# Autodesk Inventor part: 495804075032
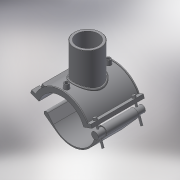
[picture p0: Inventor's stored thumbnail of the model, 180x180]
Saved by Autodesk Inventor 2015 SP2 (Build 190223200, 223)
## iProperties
Created: 2017-07
Part Number: 495804075032
Material: Generic
Description: PLASSON BRANCH SADDLE 75-32
Document SubType Name: Modeling
Designer: KIM
Density: 1 g/cm^3
Appearance: Default
Author: KIM
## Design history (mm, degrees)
derived "495804.ipt"
feature "Solid1::495804.ipt"
feature "Solid2::495804.ipt"
tag "TaggingFeature1"
body "Solid1"
body "Solid2"
other parameters: "d0" = 75, "d2" = 117, "d3" = 18.75, "d4" = 118, "d5" = 0, "d6" = 0.1, "d8" = 0, "d19" = 6, "d20" = 6, "d21" = 70.8, "d23" = 0, "d24" = 35.4, "d26" = 0, "d27" = 3, "d28" = 3, "d29" = 3, "d30" = 25, "d31" = 6, "d32" = 0, "d33" = 0, "d34" = 0.6, "d40" = 49.4, "d41" = 35.2, "d43" = 0, "d45" = 0, "d47" = 106.5, "d48" = 32, "d50" = 0, "d70" = 15, "d72" = 0, "d73" = 6, "d75" = 5, "d76" = 0, "d77" = 3.75, "d78" = 67.5, "d79" = 15, "d80" = 47.2, "d82" = 5 deg, "d84" = 4, "d85" = 14, "d86" = 0, "d87" = 3, "d88" = 0, "d89" = 1, "d90" = 1, "d91" = 94.4, "d92" = 0, "d93" = 0.5, "d94" = 39.47368, "d96" = 96.9, "d97" = 2.36, "d98" = 0, "d102" = 0.96, "d103" = 25.6, "d105" = 0, "d109" = -19.66667, "d117" = 0.32, "d120" = 140 deg, "d121" = 24.228, "d122" = 20 deg, "d124" = 57, "d126" = 0, "d143" = 78.75, "d150" = 13.5, "d159" = 4, "d161" = 1.875, "d162" = 70.8, "d163" = 0, "d167" = 15, "d168" = 43.18182, "d173" = 1, "d175" = 37.5, "d176" = 20 deg, "d177" = 5.25, "d180" = 0, "d185" = 38.35, "d186" = 38.35, "d187" = 47.5, "d188" = 6, "d189" = 5.25, "d190" = 0, "d191" = 71.25, "d202" = 0, "d216" = 106.2, "d217" = 0, "d221" = 43.66, "d222" = 5.25, "d223" = 3.15, "d224" = 37.5, "d225" = 3.15, "d227" = 10.8, "d230" = 46.5, "d236" = 20 deg, "d237" = 54.5, "d238" = 20 deg, "d239" = 5.25, "d_" = 75, "B_" = 117, "H_" = 59, "L_" = 118, "d_t" = 6, "d_1" = 32, "H_1" = 49, "d1" = 95, "d148" = 1.875, "d160" = 1.875
